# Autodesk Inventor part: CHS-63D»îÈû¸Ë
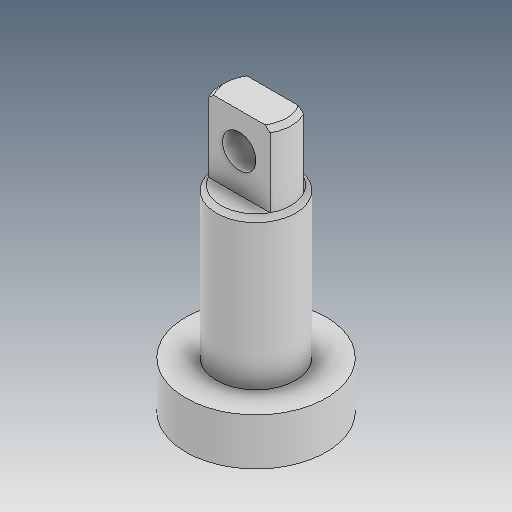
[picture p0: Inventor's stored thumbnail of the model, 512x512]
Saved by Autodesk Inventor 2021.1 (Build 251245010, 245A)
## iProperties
Created: 2019-05
Part Number: CHS-63D»îÈû¸Ë
Material: Ogólny
Document SubType Name: Modeling
Designer: user
Density: 1 g/cm^3
Appearance: Domyślna
Author: user
Revision Number: ÈÎºÎ
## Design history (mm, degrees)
feature "ÊäÈë1"
feature "ÊäÈë2"
node "Bryła1"
node "Bryła2"
